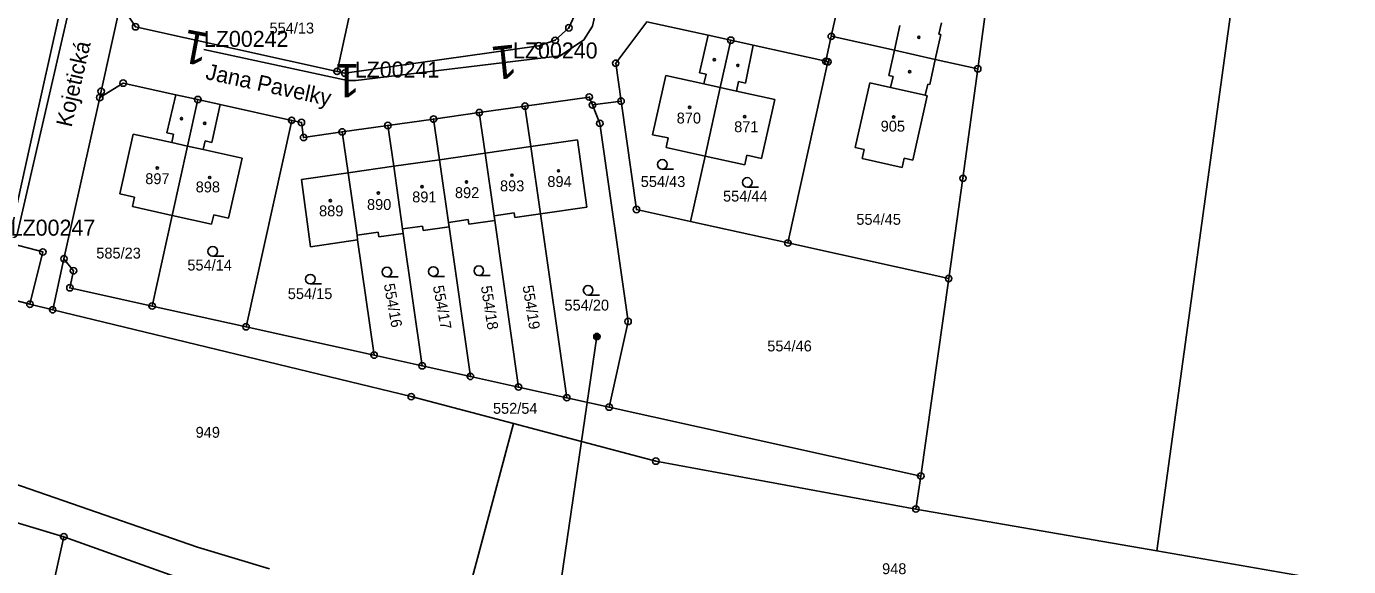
# Model space of a CAD drawing. Extents: x -738131 to -734179, y -1033447 to -1030078.
# Drawn here: x -735564.5 to -735358.2, y -1032166.9 to -1032082.6 of the extents above; entities that cross this region are included whole.
import ezdxf

# ---------------------------------------------------------------- set-up
doc = ezdxf.new("R2010")
doc.units = 0
for name, color, linetype in [('ftf_2010', 7, 'Continuous'), ('ftf_3010', 7, 'Continuous'), ('ftf_3010_ftf_3010_gtda_3015_gtda_3015_1', 7, 'Continuous'), ('ftf_nu', 7, 'Continuous'), ('Vrstva 1', 7, 'Continuous'), ('Vrstva 2', 7, 'Continuous'), ('Vrstva 3', 7, 'Continuous'), ('Vrstva 4', 7, 'Continuous'), ('Vrstva 5', 7, 'Continuous'), ('Vrstva 6', 7, 'Continuous'), ('Vrstva 8', 7, 'Continuous')]:
    doc.layers.add(name, color=color, linetype=linetype)

msp = doc.modelspace()

# ---------------------------------------------------------------- linework, layer by layer
at = {"layer": 'ftf_2010'}
for points in [[(-735488.58, -1032088.05), (-735481.17, -1032087.19), (-735477.47, -1032084.69), (-735476.12, -1032082.55), (-735473.94, -1032072.75), (-735462.96, -1032074.44)], [(-735557.79, -1032079.84), (-735565.96, -1032115.27), (-735566.66, -1032115.75)], [(-735536.8, -1032086.19), (-735514.34, -1032091.05), (-735513.08, -1032091.06)], [(-735513.08, -1032091.06), (-735488.58, -1032088.05)]]:
    msp.add_lwpolyline(points, dxfattribs=at)
at = {"layer": 'Vrstva 1'}
for points in [[(-735411.52, -1032055.82), (-735416.02, -1032089.21)], [(-735515.99, -1032089.61), (-735513.56, -1032078.67)], [(-735376.08, -1032076.89), (-735388.08, -1032164.46)], [(-735549.77, -1032079.06), (-735552.8, -1032092.72)], [(-735549.77, -1032079.06), (-735547.43, -1032082.65)], [(-735479.82, -1032082.82), (-735478.63, -1032080.19)], [(-735438.01, -1032080.23), (-735438.88, -1032084.14)], [(-735559.52, -1032081.44), (-735563.2, -1032098.02)], [(-735547.43, -1032082.65), (-735515.99, -1032089.61)], [(-735467.65, -1032081.86), (-735472.52, -1032088.35)], [(-735458.08, -1032083.98), (-735467.65, -1032081.86)], [(-735429.04, -1032086.32), (-735428.17, -1032082.43)], [(-735421.66, -1032082.01), (-735422.08, -1032083.8)], [(-735484.5, -1032085.63), (-735481.96, -1032084.76)], [(-735481.96, -1032084.76), (-735479.82, -1032082.82)], [(-735458.08, -1032083.98), (-735459.44, -1032089.82)], [(-735454.56, -1032084.75), (-735458.08, -1032083.98)], [(-735456.2, -1032092.13), (-735454.56, -1032084.75)], [(-735451.05, -1032085.54), (-735454.56, -1032084.75)], [(-735439.74, -1032088.04), (-735438.88, -1032084.14)], [(-735438.88, -1032084.14), (-735429.04, -1032086.32)], [(-735421.77, -1032083.87), (-735422.65, -1032087.74)], [(-735422.08, -1032083.8), (-735421.77, -1032083.87)], [(-735514.77, -1032089.88), (-735484.5, -1032085.63)], [(-735452.28, -1032091.44), (-735451.05, -1032085.54)], [(-735439.74, -1032088.04), (-735451.05, -1032085.54)], [(-735429.04, -1032086.32), (-735429.91, -1032090.28)], [(-735422.65, -1032087.74), (-735429.04, -1032086.32)], [(-735472.52, -1032088.35), (-735471.68, -1032094.26)], [(-735445.65, -1032116.41), (-735439.42, -1032088.11)], [(-735439.42, -1032088.11), (-735439.74, -1032088.04)], [(-735423.52, -1032091.66), (-735422.65, -1032087.74)], [(-735422.65, -1032087.74), (-735416.02, -1032089.21)], [(-735515.99, -1032089.61), (-735514.77, -1032089.88)], [(-735464.72, -1032090.25), (-735466.75, -1032099.5)], [(-735458.75, -1032091.57), (-735464.72, -1032090.25)], [(-735459.44, -1032089.82), (-735458.39, -1032090.06)], [(-735458.39, -1032090.06), (-735458.75, -1032091.57)], [(-735429.91, -1032090.28), (-735429.24, -1032090.43)], [(-735429.24, -1032090.43), (-735429.63, -1032092.14)], [(-735416.02, -1032089.21), (-735418.33, -1032106.31)], [(-735553.02, -1032093.7), (-735549.37, -1032091.44)], [(-735552.8, -1032092.72), (-735553.02, -1032093.7)], [(-735549.37, -1032091.44), (-735541.16, -1032093.26)], [(-735458.57, -1032102.84), (-735456.2, -1032092.13)], [(-735453.67, -1032092.69), (-735453.36, -1032091.21)], [(-735447.7, -1032094), (-735453.67, -1032092.69)], [(-735453.36, -1032091.21), (-735452.28, -1032091.44)], [(-735432.88, -1032091.42), (-735435.14, -1032101.48)], [(-735429.63, -1032092.14), (-735432.88, -1032091.42)], [(-735424.21, -1032093.34), (-735423.83, -1032091.59)], [(-735423.83, -1032091.59), (-735423.52, -1032091.66)], [(-735558.6, -1032118.89), (-735553.02, -1032093.7)], [(-735541.16, -1032093.26), (-735542.57, -1032099.22)], [(-735541.16, -1032093.26), (-735537.71, -1032094.02)], [(-735539.31, -1032101.27), (-735537.71, -1032094.02)], [(-735537.71, -1032094.02), (-735534.22, -1032094.79)], [(-735535.53, -1032100.7), (-735534.22, -1032094.79)], [(-735534.22, -1032094.79), (-735523.07, -1032097.26)], [(-735493.8, -1032096.05), (-735486.67, -1032095.04)], [(-735486.67, -1032095.04), (-735476.65, -1032093.62)], [(-735486.67, -1032095.04), (-735485.76, -1032101.37)], [(-735476.65, -1032093.62), (-735476.14, -1032094.86)], [(-735476.14, -1032094.86), (-735471.68, -1032094.26)], [(-735476.14, -1032094.86), (-735474.99, -1032097.73)], [(-735471.68, -1032094.26), (-735469.28, -1032111.18)], [(-735449.76, -1032103.22), (-735447.7, -1032094)], [(-735426.14, -1032103.5), (-735423.9, -1032093.41)], [(-735423.9, -1032093.41), (-735424.21, -1032093.34)], [(-735508.06, -1032098.06), (-735500.93, -1032097.06)], [(-735500.93, -1032097.06), (-735493.8, -1032096.05)], [(-735500.93, -1032097.06), (-735500.02, -1032103.41)], [(-735493.8, -1032096.05), (-735492.89, -1032102.39)], [(-735566.6, -1032113.36), (-735563.2, -1032098.02)], [(-735542.57, -1032099.22), (-735541.51, -1032099.42)], [(-735523.07, -1032097.26), (-735530.19, -1032129.49)], [(-735523.07, -1032097.26), (-735521.55, -1032097.6)], [(-735521.55, -1032097.6), (-735521.21, -1032099.93)], [(-735521.21, -1032099.93), (-735515.19, -1032099.07)], [(-735515.19, -1032099.07), (-735508.06, -1032098.06)], [(-735515.19, -1032099.07), (-735514.28, -1032105.46)], [(-735508.06, -1032098.06), (-735507.15, -1032104.43)], [(-735474.99, -1032097.73), (-735470.58, -1032128.66)], [(-735547.8, -1032099.4), (-735549.88, -1032108.74)], [(-735541.76, -1032100.73), (-735547.8, -1032099.4)], [(-735541.51, -1032099.42), (-735541.76, -1032100.73)], [(-735541.71, -1032112.11), (-735539.31, -1032101.27)], [(-735536.86, -1032101.82), (-735536.56, -1032100.47)], [(-735536.56, -1032100.47), (-735535.53, -1032100.7)], [(-735485.76, -1032101.37), (-735478.47, -1032100.32)], [(-735478.47, -1032100.32), (-735477, -1032110.82)], [(-735466.75, -1032099.5), (-735464.35, -1032100.01)], [(-735464.35, -1032100.01), (-735464.66, -1032101.51)], [(-735530.8, -1032103.16), (-735536.86, -1032101.82)], [(-735532.92, -1032112.52), (-735530.8, -1032103.16)], [(-735498.63, -1032113.19), (-735500.02, -1032103.41)], [(-735491.5, -1032112.16), (-735492.89, -1032102.39)], [(-735485.76, -1032101.37), (-735484.26, -1032111.86)], [(-735464.66, -1032101.51), (-735458.57, -1032102.84)], [(-735458.57, -1032102.84), (-735460.83, -1032113.05)], [(-735458.57, -1032102.84), (-735452.39, -1032104.2)], [(-735452.39, -1032104.2), (-735452.06, -1032102.72)], [(-735452.06, -1032102.72), (-735449.76, -1032103.22)], [(-735435.14, -1032101.48), (-735433.74, -1032101.79)], [(-735433.74, -1032101.79), (-735434.07, -1032103.24)], [(-735434.07, -1032103.24), (-735427.83, -1032104.63)], [(-735427.83, -1032104.63), (-735427.51, -1032103.19)], [(-735427.51, -1032103.19), (-735426.14, -1032103.5)], [(-735521.56, -1032106.5), (-735514.28, -1032105.46)], [(-735512.88, -1032115.21), (-735514.28, -1032105.46)], [(-735505.76, -1032114.19), (-735507.15, -1032104.43)], [(-735520.14, -1032116.99), (-735521.56, -1032106.5)], [(-735418.33, -1032106.31), (-735420.56, -1032121.97)], [(-735549.88, -1032108.74), (-735547.58, -1032109.25)], [(-735547.58, -1032109.25), (-735547.91, -1032110.71)], [(-735547.91, -1032110.71), (-735541.71, -1032112.11)], [(-735477, -1032110.82), (-735484.26, -1032111.86)], [(-735469.28, -1032111.18), (-735460.83, -1032113.05)], [(-735544.84, -1032126.25), (-735541.71, -1032112.11)], [(-735541.71, -1032112.11), (-735535.58, -1032113.49)], [(-735535.58, -1032113.49), (-735535.22, -1032112.02)], [(-735535.22, -1032112.02), (-735532.92, -1032112.52)], [(-735495.52, -1032112.73), (-735498.63, -1032113.19)], [(-735498.63, -1032113.19), (-735498.52, -1032113.9)], [(-735495.42, -1032113.46), (-735495.52, -1032112.73)], [(-735491.4, -1032112.88), (-735495.42, -1032113.46)], [(-735488.34, -1032111.71), (-735491.5, -1032112.16)], [(-735491.5, -1032112.16), (-735491.4, -1032112.88)], [(-735491.4, -1032112.88), (-735487.68, -1032138.9)], [(-735488.24, -1032112.43), (-735488.34, -1032111.71)], [(-735484.26, -1032111.86), (-735488.24, -1032112.43)], [(-735484.26, -1032111.86), (-735480.15, -1032140.57)], [(-735460.83, -1032113.05), (-735445.65, -1032116.41)], [(-735570.32, -1032115.63), (-735561.9, -1032117.81)], [(-735509.57, -1032114.74), (-735512.88, -1032115.21)], [(-735512.88, -1032115.21), (-735512.78, -1032115.94)], [(-735509.47, -1032115.47), (-735509.57, -1032114.74)], [(-735505.66, -1032114.92), (-735509.47, -1032115.47)], [(-735502.66, -1032113.76), (-735505.76, -1032114.19)], [(-735505.76, -1032114.19), (-735505.66, -1032114.92)], [(-735505.66, -1032114.92), (-735502.71, -1032135.58)], [(-735502.56, -1032114.47), (-735502.66, -1032113.76)], [(-735498.52, -1032113.9), (-735502.56, -1032114.47)], [(-735498.52, -1032113.9), (-735495.19, -1032137.24)], [(-735561.9, -1032117.81), (-735563.91, -1032125.97)], [(-735512.78, -1032115.94), (-735520.14, -1032116.99)], [(-735512.78, -1032115.94), (-735510.21, -1032133.91)], [(-735445.65, -1032116.41), (-735420.56, -1032121.97)], [(-735563.91, -1032125.97), (-735591.5, -1032118.85)], [(-735558.6, -1032118.89), (-735560.36, -1032126.83)], [(-735557.12, -1032120.74), (-735558.6, -1032118.89)], [(-735557.68, -1032123.4), (-735557.12, -1032120.74)], [(-735420.56, -1032121.97), (-735424.91, -1032152.8)], [(-735544.84, -1032126.25), (-735557.68, -1032123.4)], [(-735560.36, -1032126.83), (-735563.91, -1032125.97)], [(-735504.42, -1032140.4), (-735560.36, -1032126.83)], [(-735530.19, -1032129.49), (-735544.84, -1032126.25)], [(-735510.21, -1032133.91), (-735530.19, -1032129.49)], [(-735470.58, -1032128.66), (-735473.54, -1032142.04)], [(-735510.21, -1032133.91), (-735502.71, -1032135.58)], [(-735495.19, -1032137.24), (-735502.71, -1032135.58)], [(-735487.68, -1032138.9), (-735495.19, -1032137.24)], [(-735488.47, -1032144.61), (-735504.42, -1032140.4)], [(-735487.68, -1032138.9), (-735480.15, -1032140.57)], [(-735473.54, -1032142.04), (-735480.15, -1032140.57)], [(-735473.54, -1032142.04), (-735424.91, -1032152.8)], [(-735595.43, -1032143.92), (-735537.79, -1032163.9)], [(-735488.47, -1032144.61), (-735496.54, -1032174.79)], [(-735466.26, -1032150.47), (-735488.47, -1032144.61)], [(-735597.2, -1032150.66), (-735558.62, -1032162.27)], [(-735425.68, -1032157.95), (-735466.26, -1032150.47)], [(-735424.91, -1032152.8), (-735425.68, -1032157.95)], [(-735425.68, -1032157.95), (-735388.08, -1032164.46)], [(-735558.62, -1032162.27), (-735569.86, -1032212.71)], [(-735558.62, -1032162.27), (-735519.06, -1032176.44)], [(-735537.79, -1032163.9), (-735526.55, -1032167.3)], [(-735388.08, -1032164.46), (-735358.17, -1032169.69)]]:
    msp.add_lwpolyline(points, dxfattribs=at)
at = {"layer": 'Vrstva 3'}
for p, q in [((-735465.24, -1032104.89), (-735463.49, -1032104.89)), ((-735451.99, -1032107.7), (-735450.24, -1032107.7)), ((-735535.39, -1032118.47), (-735533.64, -1032118.47)), ((-735508.22, -1032121.69), (-735506.47, -1032121.69)), ((-735500.98, -1032121.62), (-735499.23, -1032121.62)), ((-735493.87, -1032121.49), (-735492.12, -1032121.49)), ((-735520.17, -1032122.81), (-735518.42, -1032122.81)), ((-735476.82, -1032124.54), (-735475.07, -1032124.54))]:
    msp.add_line(p, q, dxfattribs=at)
for centre in [(-735465.24, -1032104.14), (-735451.99, -1032106.95), (-735535.39, -1032117.72), (-735520.17, -1032122.06), (-735508.22, -1032120.94), (-735500.98, -1032120.87), (-735493.87, -1032120.74), (-735476.82, -1032123.79)]:
    msp.add_circle(centre, 0.75, dxfattribs=at)
at = {"layer": 'Vrstva 4'}
for points in [[(-735458.75, -1032091.57), (-735456.2, -1032092.13)], [(-735456.2, -1032092.13), (-735453.67, -1032092.69)], [(-735429.63, -1032092.14), (-735424.21, -1032093.34)], [(-735541.76, -1032100.73), (-735539.31, -1032101.27)], [(-735539.31, -1032101.27), (-735536.86, -1032101.82)], [(-735507.15, -1032104.43), (-735500.02, -1032103.41)], [(-735500.02, -1032103.41), (-735492.89, -1032102.39)], [(-735492.89, -1032102.39), (-735485.76, -1032101.37)], [(-735514.28, -1032105.46), (-735507.15, -1032104.43)]]:
    msp.add_lwpolyline(points, dxfattribs=at)
at = {"layer": 'Vrstva 5'}
for centre in [(-735425.22, -1032084.3), (-735457.13, -1032087.79), (-735453.46, -1032088.69), (-735426.65, -1032089.67), (-735460.99, -1032095.24), (-735540.26, -1032096.99), (-735452.39, -1032096.68), (-735429.15, -1032096.75), (-735536.64, -1032097.73), (-735544.05, -1032104.72), (-735481.44, -1032105.15), (-735535.86, -1032106.18), (-735502.73, -1032107.61), (-735495.8, -1032106.89), (-735488.7, -1032105.82), (-735517.04, -1032109.79), (-735509.55, -1032108.62)]:
    msp.add_circle(centre, 0.175, dxfattribs=at)
at = {"layer": 'Vrstva 6'}
msp.add_lwpolyline([(-735484.07, -1032190.06), (-735475.45, -1032131.03)], dxfattribs=at)
for radius in [0.5, 0.4, 0.3, 0.2, 0.1]:
    msp.add_circle((-735475.45, -1032131.03), radius, dxfattribs=at)
at = {"layer": 'Vrstva 8'}
for centre, radius in [((-735547.43, -1032082.65), 0.5), ((-735547.43, -1032082.65), 0.0303), ((-735479.82, -1032082.82), 0.5), ((-735479.82, -1032082.82), 0.0303), ((-735481.96, -1032084.76), 0.5), ((-735481.96, -1032084.76), 0.0303), ((-735454.56, -1032084.75), 0.5), ((-735454.56, -1032084.75), 0.0303), ((-735438.88, -1032084.14), 0.5), ((-735438.88, -1032084.14), 0.0303), ((-735484.5, -1032085.63), 0.5), ((-735484.5, -1032085.63), 0.0303), ((-735472.52, -1032088.35), 0.5), ((-735472.52, -1032088.35), 0.0303), ((-735439.74, -1032088.04), 0.5), ((-735439.42, -1032088.11), 0.5), ((-735439.74, -1032088.04), 0.0303), ((-735439.42, -1032088.11), 0.0303), ((-735416.02, -1032089.21), 0.5), ((-735549.37, -1032091.44), 0.5), ((-735515.99, -1032089.61), 0.5), ((-735515.99, -1032089.61), 0.0303), ((-735514.77, -1032089.88), 0.5), ((-735514.77, -1032089.88), 0.0303), ((-735416.02, -1032089.21), 0.0303), ((-735552.8, -1032092.72), 0.5), ((-735552.8, -1032092.72), 0.0303), ((-735549.37, -1032091.44), 0.0303), ((-735553.02, -1032093.7), 0.5), ((-735553.02, -1032093.7), 0.0303), ((-735537.71, -1032094.02), 0.5), ((-735537.71, -1032094.02), 0.0303), ((-735486.67, -1032095.04), 0.5), ((-735486.67, -1032095.04), 0.0303), ((-735476.65, -1032093.62), 0.5), ((-735476.65, -1032093.62), 0.0303), ((-735476.14, -1032094.86), 0.5), ((-735476.14, -1032094.86), 0.0303), ((-735471.68, -1032094.26), 0.5), ((-735471.68, -1032094.26), 0.0303), ((-735523.07, -1032097.26), 0.5), ((-735523.07, -1032097.26), 0.0303), ((-735521.55, -1032097.6), 0.5), ((-735500.93, -1032097.06), 0.5), ((-735500.93, -1032097.06), 0.0303), ((-735493.8, -1032096.05), 0.5), ((-735493.8, -1032096.05), 0.0303), ((-735474.99, -1032097.73), 0.5), ((-735521.55, -1032097.6), 0.0303), ((-735515.19, -1032099.07), 0.5), ((-735515.19, -1032099.07), 0.0303), ((-735508.06, -1032098.06), 0.5), ((-735508.06, -1032098.06), 0.0303), ((-735474.99, -1032097.73), 0.0303), ((-735521.21, -1032099.93), 0.5), ((-735521.21, -1032099.93), 0.0303), ((-735418.33, -1032106.31), 0.5), ((-735418.33, -1032106.31), 0.0303), ((-735469.28, -1032111.18), 0.5), ((-735469.28, -1032111.18), 0.0303), ((-735561.9, -1032117.81), 0.5), ((-735561.9, -1032117.81), 0.0303), ((-735445.65, -1032116.41), 0.5), ((-735445.65, -1032116.41), 0.0303), ((-735558.6, -1032118.89), 0.5), ((-735558.6, -1032118.89), 0.0303), ((-735557.12, -1032120.74), 0.5), ((-735557.12, -1032120.74), 0.0303), ((-735420.56, -1032121.97), 0.5), ((-735420.56, -1032121.97), 0.0303), ((-735557.68, -1032123.4), 0.5), ((-735557.68, -1032123.4), 0.0303), ((-735563.91, -1032125.97), 0.5), ((-735563.91, -1032125.97), 0.0303), ((-735544.84, -1032126.25), 0.5), ((-735560.36, -1032126.83), 0.5), ((-735560.36, -1032126.83), 0.0303), ((-735544.84, -1032126.25), 0.0303), ((-735470.58, -1032128.66), 0.5), ((-735530.19, -1032129.49), 0.5), ((-735530.19, -1032129.49), 0.0303), ((-735470.58, -1032128.66), 0.0303), ((-735510.21, -1032133.91), 0.5), ((-735510.21, -1032133.91), 0.0303), ((-735502.71, -1032135.58), 0.5), ((-735502.71, -1032135.58), 0.0303), ((-735495.19, -1032137.24), 0.5), ((-735495.19, -1032137.24), 0.0303), ((-735487.68, -1032138.9), 0.5), ((-735504.42, -1032140.4), 0.5), ((-735504.42, -1032140.4), 0.0303), ((-735487.68, -1032138.9), 0.0303), ((-735480.15, -1032140.57), 0.5), ((-735480.15, -1032140.57), 0.0303), ((-735473.54, -1032142.04), 0.5), ((-735473.54, -1032142.04), 0.0303), ((-735466.26, -1032150.47), 0.5), ((-735466.26, -1032150.47), 0.0303), ((-735424.91, -1032152.8), 0.5), ((-735424.91, -1032152.8), 0.0303), ((-735425.68, -1032157.95), 0.5), ((-735425.68, -1032157.95), 0.0303), ((-735558.62, -1032162.27), 0.5), ((-735558.62, -1032162.27), 0.0303)]:
    msp.add_circle(centre, radius, dxfattribs=at)

# ---------------------------------------------------------------- texts
at = {"layer": 'ftf_3010'}
for rotation, p in [(169.2933, (-735535.68, -1032083.76)), (185.8801, (-735488.2, -1032085.4)), (180, (-735512.43, -1032088.46))]:
    msp.add_text('1', height=5.2, rotation=rotation, dxfattribs=at).set_placement(p)
at = {"layer": 'ftf_3010_ftf_3010_gtda_3015_gtda_3015_1'}
for s, p in [('LZ00242', (-735536.77, -1032085.79)), ('LZ00240', (-735488.54, -1032087.6)), ('LZ00241', (-735513.23, -1032090.58)), ('LZ00247', (-735566.92, -1032115.27))]:
    msp.add_text(s, height=2.5, dxfattribs=at).set_placement(p)
at = {"layer": 'ftf_nu'}
for s, rotation, p in [('Kojetická', 77.2206, (-735557.43, -1032098.44)), ('Jana Pavelky', 347.6641, (-735536.64, -1032090.79))]:
    msp.add_text(s, height=2.5, rotation=rotation, dxfattribs=at).set_placement(p)
at = {"layer": 'Vrstva 2'}
for s, p in [('554/13', (-735526.53, -1032083.7)), ('870', (-735463, -1032097.75)), ('871', (-735454.03, -1032099.11)), ('905', (-735431.17, -1032099.02)), ('897', (-735545.92, -1032107.22)), ('898', (-735538.05, -1032108.51)), ('893', (-735490.57, -1032108.34)), ('894', (-735483.18, -1032107.67)), ('554/43', (-735468.61, -1032107.67)), ('890', (-735511.32, -1032111.25)), ('891', (-735504.27, -1032110.07)), ('892', (-735497.6, -1032109.4)), ('554/44', (-735455.77, -1032109.94)), ('889', (-735518.8, -1032112.25)), ('554/45', (-735434.97, -1032113.57)), ('585/23', (-735553.56, -1032118.84)), ('554/14', (-735539.35, -1032120.71)), ('554/15', (-735523.68, -1032125.17)), ('554/20', (-735480.51, -1032126.96)), ('554/46', (-735448.87, -1032133.34)), ('552/54', (-735491.67, -1032143.08)), ('949', (-735538.06, -1032146.82)), ('948', (-735430.95, -1032168.12))]:
    msp.add_text(s, height=1.7, dxfattribs=at).set_placement(p)
for s, rotation, p in [('554/16', 280.2363, (-735508.71, -1032122.88)), ('554/17', 280.5798, (-735501.05, -1032123.19)), ('554/18', 279.0889, (-735493.57, -1032123.21)), ('554/19', 279.0187, (-735487.06, -1032123.14))]:
    msp.add_text(s, height=1.7, rotation=rotation, dxfattribs=at).set_placement(p)

doc.saveas('drawing.dxf')
